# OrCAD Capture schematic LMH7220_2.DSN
size A
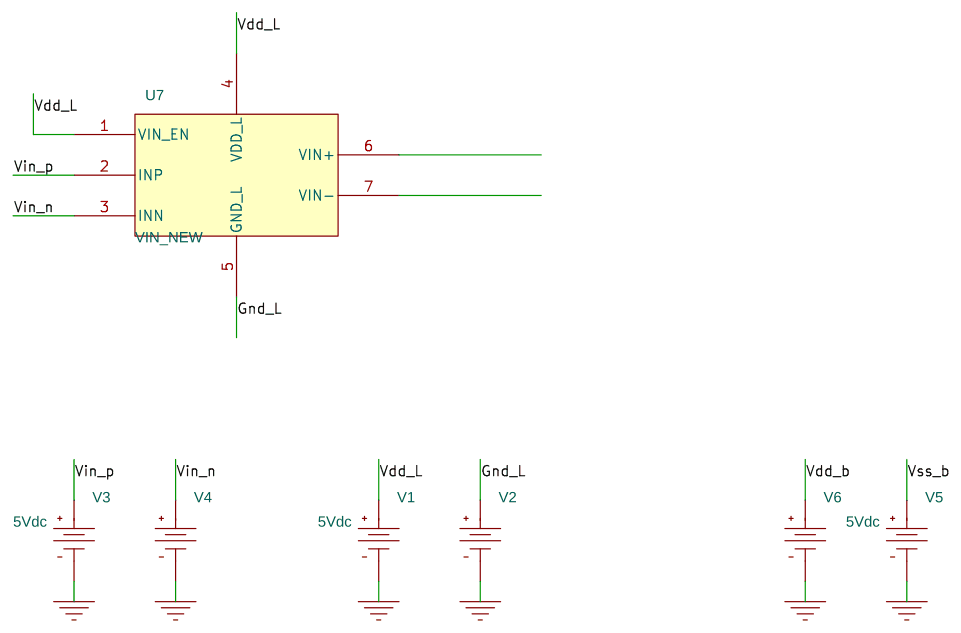
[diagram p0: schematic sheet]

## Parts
U7  VIN_NEW
V1  VDC
V2  VDC
V3  VDC
V4  VDC
V5  VDC
V6  VDC

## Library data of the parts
U7 = VIN_NEW_0
V1 V3 V5 = VDC: DC: 5Vdc
V2 V4 V6 = VDC

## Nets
Gnd_L: U7.5(GND_L) V2.0(+)
Vdd_b: V6.0(+)
Vdd_L: U7.1(VIN_EN) U7.4(VDD_L) V1.0(+)
Vin_n: U7.3(INN) V4.0(+)
Vin_p: U7.2(INP) V3.0(+)
Vss_b: V5.0(+)
0: V1.1(-) V2.1(-) V3.1(-) V4.1(-) V5.1(-) V6.1(-)

Not connected (* = marked no-connect by the designer): U7 6(VIN+) 7(VIN-)
